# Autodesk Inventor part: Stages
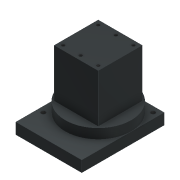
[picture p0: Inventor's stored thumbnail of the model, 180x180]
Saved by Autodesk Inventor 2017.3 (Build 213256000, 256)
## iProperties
Part Number: Stages
Material: 鉄、ダクタイル
Document SubType Name: Modeling
Designer: kyushu-hep
Density: 7.15 g/cm^3
Appearance: 鉄 灰色
Author: kyushu-hep
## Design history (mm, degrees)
sketch "スケッチ1"
  geometry: L1 (30, -37.5)-(-30, -37.5); L2 (-30, -37.5)-(-30, 37.5); L3 (-30, 37.5)-(30, 37.5); L4 (30, 37.5)-(30, -37.5); L5 (30, -37.5)-(-30, 37.5); L6 (-30, -37.5)-(30, 37.5); 1 further point
  constraints: 12 end point, 2 midpoint, 2 parallel, 1 horizontal, 1 perpendicular
  dimensions: "d0" = 60 distance of L2.end L3.end; "d1" = 75 distance of L3.end L1.start
extrude "押し出し1" new body sketch "スケッチ1" distance "d2" = 10; taper "d3" = 0 deg
sketch "スケッチ2"
  geometry: L1 (-30, 37.5)-(-30, -37.5) reference; L2 (30, 37.5)-(-30, 37.5) reference; C1 r 30 at (0, 7.5); 1 further point
  constraints: 2 tangent, 1 centre point
  dimensions: "d4" = 60 diameter of C1
extrude "押し出し2" join sketch "スケッチ2" distance "d5" = 9; taper "d6" = 0 deg
sketch "スケッチ3"
  geometry: L1 (-30, 7.5)-(-30, -37.5) reference; L2 (-30, 37.5)-(-30, 7.5) reference; L3 (0, 37.5)-(-30, 37.5) reference; L4 (30, 37.5)-(0, 37.5) reference; C1 r 2 at (-25, -17.5); C2 r 2 at (-25, 32.5); C3 r 2 at (25, 32.5); 1 further point
  constraints: 3 centre point
  dimensions: "d7" = 4 diameter of C1; "d8" = 4 diameter of C2; "d9" = 4 diameter of C3; "d10" = 50 distance of C1.centre C2.centre; "d11" = 5 distance from line of L1 C1.centre; "d12" = 5 distance from line of L2 C2.centre; "d13" = 5 distance from line of L3 C2.centre; "d14" = 50 distance of C2.centre C3.centre; "d15" = 5 distance from line of L4 C3.centre
extrude "押し出し3" cut sketch "スケッチ3" distance "d16" = 10; taper "d17" = 0 deg
sketch "スケッチ4"
  geometry: L1 (20, 20)-(-20, 20); L2 (-20, 20)-(-20, -20); L3 (-20, -20)-(20, -20); L4 (20, -20)-(20, 20); L5 (20, 20)-(-20, -20); L6 (-20, 20)-(20, -20); 2 further points
  constraints: 12 end point, 2 midpoint, 2 parallel, 1 horizontal, 1 perpendicular
  dimensions: "d18" = 40 distance of L3.end L2.end; "d19" = 40 distance of L2.end L1.end
extrude "押し出し4" join sketch "スケッチ4" distance "d20" = 44; taper "d21" = 0 deg
sketch "スケッチ5"
  geometry: L1 (20, 20)-(-20, 20) reference; L2 (-20, -20)-(20, -20) reference; L3 (-20, 20)-(20, 20); L4 (20, 20)-(20, -20); L5 (20, -20)-(-20, -20); L6 (-20, -20)-(-20, 20); C1 r 1.5 at (-16, 16); C2 r 1.5 at (0, 16); C3 r 1.5 at (16, 16); C4 r 1.5 at (-16, -16); C5 r 1.5 at (0, -16); C6 r 1.5 at (16, -16); 1 further point
  constraints: 8 end point, 6 centre point, 2 horizontal, 2 parallel, 1 perpendicular, 1 vertical, 10 other
  dimensions: "d22" = 3 diameter of C1; "d23" = 23.5 vertical distance of point (0, -7.5) C1.centre; "d24" = 16 horizontal distance of C1.centre point (0, -7.5); "d27" = 16 distance of C1.centre C2.centre; "d30" = 32 distance of C1.centre C4.centre
extrude "押し出し5" cut sketch "スケッチ5" distance "d33" = 7; taper "d34" = 0 deg
feature "ねじ1" dims "d35" = 10, "d36" = 0
feature "ねじ2" dims "d37" = 10, "d38" = 0
feature "ねじ3" dims "d39" = 10, "d40" = 0
feature "ねじ4" dims "d41" = 10, "d42" = 0
feature "ねじ5" dims "d43" = 10, "d44" = 0
feature "ねじ6" dims "d45" = 10, "d46" = 0
feature "ねじ7" dims "d47" = 10, "d48" = 0
feature "ねじ8" dims "d49" = 10, "d50" = 0
feature "ねじ9" dims "d51" = 10, "d52" = 0
node "ソリッド1"
